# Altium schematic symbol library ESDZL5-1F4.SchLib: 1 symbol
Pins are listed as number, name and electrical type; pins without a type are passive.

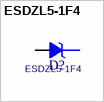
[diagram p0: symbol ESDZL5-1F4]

## ESDZL5-1F4
designator D?
footprint ST_0201-F4
pins: 1 K, 2 A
